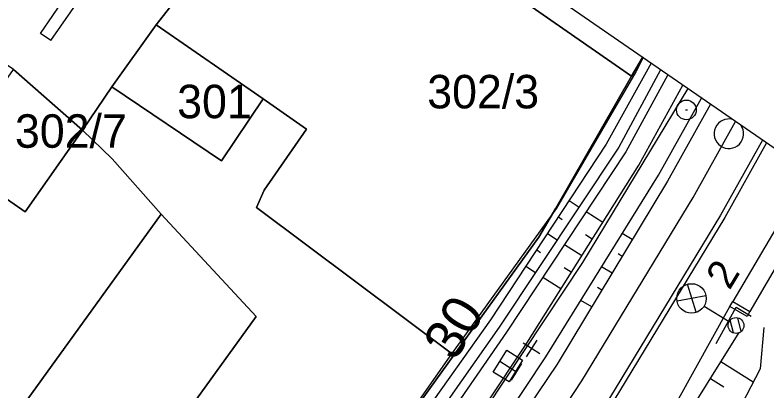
# Model space of a CAD drawing. Extents: x -558195 to -557985, y -1073457 to -1073198.
# Drawn here: x -558113.53 to -558075.28, y -1073322.92 to -1073303.83 of the extents above; entities that cross this region are included whole.
import ezdxf

# ---------------------------------------------------------------- set-up
doc = ezdxf.new("R2010")
doc.units = 0
for name, color, linetype in [('Default', 7, 'Continuous'), ('DWG-zabzař', 7, 'Continuous'), ('El2015-Sikl - patka - rampa', 7, 'Continuous'), ('El2015-Trakce', 7, 'Continuous'), ('Elektro nadzemní', 7, 'Continuous'), ('Kolej', 7, 'Continuous'), ('Nástupiště', 7, 'Continuous'), ('Návěst místo trati', 7, 'Continuous'), ('Plot - zábradlí', 7, 'Continuous'), ('Přejezd - štěrkové lože', 7, 'Continuous'), ('Rámeček stavby', 7, 'Continuous'), ('Sonda - šrafa - vrstevnice', 7, 'Continuous'), ('Svazek obcí údolí Desné', 7, 'Continuous'), ('Terén', 7, 'Continuous'), ('Vedení neurčené', 7, 'Continuous'), ('Vrstva 15', 7, 'Continuous'), ('Vrstva 16', 7, 'Continuous'), ('Vrstva 18', 7, 'Continuous'), ('Vrstva 28', 7, 'Continuous'), ('Zpevněná plocha - svah', 7, 'Continuous')]:
    doc.layers.add(name, color=color, linetype=linetype)

msp = doc.modelspace()

# ---------------------------------------------------------------- linework, layer by layer
at = {"layer": 'Default'}
for p, q in [((-558112.232, -1073304.762), (-558105.931, -1073295.618)), ((-558111.7, -1073305.129), (-558105.398, -1073295.985)), ((-558111.7, -1073305.129), (-558112.232, -1073304.762))]:
    msp.add_line(p, q, dxfattribs=at)
at = {"layer": 'DWG-zabzař'}
for p, q in [((-558079.305, -1073307.564), (-558084.66, -1073316.4)), ((-558084.66, -1073316.4), (-558091.64, -1073326.89))]:
    msp.add_line(p, q, dxfattribs=at)
at = {"layer": 'El2015-Sikl - patka - rampa'}
for p, q in [((-558088.512, -1073320.845), (-558087.712, -1073321.364)), ((-558088.401, -1073322.455), (-558089.212, -1073321.963))]:
    msp.add_line(p, q, dxfattribs=at)
for points in [[(-558087.712, -1073321.364), (-558088.401, -1073322.455), (-558089.212, -1073321.963), (-558088.512, -1073320.845), (-558087.712, -1073321.364)], [(-558089.212, -1073321.963), (-558089.212, -1073321.963), (-558088.512, -1073320.845), (-558088.512, -1073320.845)]]:
    msp.add_lwpolyline(points, dxfattribs=at)
at = {"layer": 'El2015-Trakce'}
for p, q in [((-558089.126, -1073321.835), (-558088.595, -1073320.988)), ((-558088.861, -1073321.412), (-558088.013, -1073321.942)), ((-558088.279, -1073322.366), (-558087.748, -1073321.519))]:
    msp.add_line(p, q, dxfattribs=at)
at = {"layer": 'Elektro nadzemní'}
for p, q in [((-558078.879, -1073318.925), (-558079.325, -1073317.502)), ((-558079.852, -1073318.351), (-558078.385, -1073318.079)), ((-558078.479, -1073318.608), (-558077.197, -1073319.387)), ((-558076.989, -1073319.969), (-558077.146, -1073319.324)), ((-558076.596, -1073319.894), (-558076.763, -1073319.207))]:
    msp.add_line(p, q, dxfattribs=at)
for centre, radius in [((-558079.12, -1073318.221), 0.749), ((-558076.855, -1073319.595), 0.4), ((-558076.855, -1073319.595), 0.4)]:
    msp.add_circle(centre, radius, dxfattribs=at)
at = {"layer": 'Kolej'}
msp.add_lwpolyline([(-558162.085, -1073435.464), (-558155.66, -1073426.127), (-558147.216, -1073413.854), (-558143.692, -1073408.727), (-558141.06, -1073404.904), (-558137.302, -1073399.438), (-558134.569, -1073395.461), (-558131.717, -1073391.307), (-558124.893, -1073381.375), (-558115.4, -1073367.564), (-558106.183, -1073354.164), (-558097.487, -1073341.511), (-558095.261, -1073338.268), (-558090.946, -1073331.927), (-558084.696, -1073322.399), (-558079.035, -1073313.091), (-558076.876, -1073309.237)], dxfattribs=at)
at = {"layer": 'Nástupiště'}
for points in [[(-558075.504, -1073310.182), (-558077.642, -1073314), (-558083.287, -1073323.291), (-558088.119, -1073330.713), (-558093.699, -1073338.955)], [(-558075.301, -1073310.322), (-558077.424, -1073314.112), (-558083.069, -1073323.403), (-558087.901, -1073330.825), (-558093.497, -1073339.112), (-558093.633, -1073339)], [(-558074.438, -1073314.006), (-558077.015, -1073318.379), (-558076.161, -1073318.88)], [(-558076.161, -1073318.88), (-558076.297, -1073319.14), (-558077.164, -1073318.639), (-558077.015, -1073318.379)], [(-558090.573, -1073339.885), (-558085.54, -1073332.431), (-558080.709, -1073325.01), (-558077.164, -1073318.639)]]:
    msp.add_lwpolyline(points, dxfattribs=at)
at = {"layer": 'Návěst místo trati'}
for p, q in [((-558079.431, -1073308.647), (-558079.331, -1073308.647)), ((-558086.99, -1073320.342), (-558087.526, -1073321.186)), ((-558086.836, -1073321.032), (-558087.68, -1073320.496))]:
    msp.add_line(p, q, dxfattribs=at)
msp.add_circle((-558079.381, -1073308.647), 0.5, dxfattribs=at)
msp.add_arc((-558077.223, -1073309.856), 0.75, 75.0246, 35.8535, dxfattribs=at)
at = {"layer": 'Plot - zábradlí'}
for points in [[(-558081.585, -1073305.993), (-558081.958, -1073306.712), (-558085.995, -1073313.64), (-558091.417, -1073321.151), (-558105.2, -1073340.829), (-558131.731, -1073378.073), (-558133.048, -1073381.894), (-558138.367, -1073389.952)], [(-558077.861, -1073320.516), (-558076.84, -1073318.669), (-558076.089, -1073319.12)]]:
    msp.add_lwpolyline(points, dxfattribs=at)
at = {"layer": 'Přejezd - štěrkové lože'}
for p, q in [((-558082.13, -1073315.231), (-558082.64, -1073314.923)), ((-558082.647, -1073316.087), (-558082.855, -1073315.961)), ((-558083.163, -1073316.943), (-558083.695, -1073316.622)), ((-558083.68, -1073317.799), (-558083.897, -1073317.668)), ((-558084.197, -1073318.655), (-558084.749, -1073318.322))]:
    msp.add_line(p, q, dxfattribs=at)
for points in [[(-558134.688, -1073392.469), (-558133.239, -1073389.979), (-558128.353, -1073382.563), (-558117.195, -1073366.537), (-558107.127, -1073351.64), (-558099.301, -1073340.237), (-558092.768, -1073330.583), (-558086.524, -1073321.182), (-558080.801, -1073311.959), (-558078.61, -1073308.043)], [(-558078.156, -1073308.355), (-558080.336, -1073312.26), (-558085.948, -1073321.555), (-558092.305, -1073330.965), (-558098.739, -1073340.644), (-558106.694, -1073352.203), (-558116.612, -1073366.808), (-558126.104, -1073380.52), (-558132.827, -1073390.228), (-558134.688, -1073392.469)]]:
    msp.add_lwpolyline(points, dxfattribs=at)
at = {"layer": 'Rámeček stavby'}
msp.add_lwpolyline([(-558106.904, -1073288.53), (-558048.067, -1073329.06), (-558134.478, -1073454.503), (-558193.315, -1073413.973)], close=True, dxfattribs=at)
at = {"layer": 'Sonda - šrafa - vrstevnice'}
for p, q in [((-558085.34, -1073313.249), (-558084.838, -1073313.58)), ((-558083.634, -1073314.358), (-558084.477, -1073313.826)), ((-558085.891, -1073314.084), (-558085.692, -1073314.215)), ((-558086.442, -1073314.918), (-558085.947, -1073315.244)), ((-558084.167, -1073315.204), (-558084.512, -1073314.986)), ((-558084.7, -1073316.05), (-558085.582, -1073315.494)), ((-558086.993, -1073315.752), (-558086.796, -1073315.882)), ((-558087.543, -1073316.587), (-558087.056, -1073316.909)), ((-558085.233, -1073316.896), (-558085.593, -1073316.669)), ((-558085.766, -1073317.742), (-558086.686, -1073317.162)), ((-558077.628, -1073321.432), (-558075.98, -1073322.461)), ((-558078.158, -1073322.281), (-558077.471, -1073322.71))]:
    msp.add_line(p, q, dxfattribs=at)
at = {"layer": 'Svazek obcí údolí Desné'}
msp.add_lwpolyline([(-558167.537, -1073431.708), (-558157.08, -1073415.91), (-558144.45, -1073397.61), (-558143.83, -1073396.83), (-558140.29, -1073392.34), (-558139.67, -1073391.56), (-558138.4, -1073389.94), (-558132.32, -1073380.12), (-558131.71, -1073378.11), (-558099.53, -1073332.65), (-558091.21, -1073321.1), (-558086.89, -1073315.11), (-558086.02, -1073313.63), (-558082.18, -1073306.93), (-558081.607, -1073305.978)], dxfattribs=at)
at = {"layer": 'Terén'}
for points in [[(-558081.18, -1073306.272), (-558083.456, -1073310.395), (-558089.337, -1073319.304), (-558095.797, -1073328.403), (-558102.651, -1073337.801)], [(-558080.693, -1073306.608), (-558082.815, -1073310.544), (-558088.899, -1073319.675), (-558095.32, -1073328.817), (-558102.006, -1073338.385), (-558110.752, -1073350.405)], [(-558080.325, -1073306.861), (-558082.46, -1073310.779), (-558088.525, -1073319.94), (-558094.874, -1073329.104), (-558101.386, -1073338.86), (-558109.505, -1073351.261), (-558119.112, -1073365.018), (-558130.44, -1073381.204), (-558136.541, -1073389.319), (-558138.367, -1073389.952)], [(-558141.446, -1073388.086), (-558138.672, -1073391.073), (-558136.007, -1073391.106), (-558129.583, -1073381.786), (-558118.096, -1073365.959), (-558108.152, -1073351.289), (-558100.315, -1073339.526), (-558093.751, -1073329.892), (-558087.503, -1073320.498), (-558081.802, -1073311.451), (-558079.554, -1073307.392)], [(-558075.447, -1073319.704), (-558075.635, -1073321.794), (-558078.439, -1073327.212), (-558083.002, -1073334.109), (-558086.852, -1073340.18), (-558089.38, -1073342.195)], [(-558090.522, -1073340.781), (-558084.963, -1073332.785), (-558079.942, -1073325.14), (-558076.703, -1073319.95)]]:
    msp.add_lwpolyline(points, dxfattribs=at)
at = {"layer": 'Vrstva 15'}
for points in [[(-558107.451, -1073289.376), (-558099.14, -1073295.15), (-558106.35, -1073304.33), (-558108.61, -1073307.47), (-558110.09, -1073309.68), (-558113.61, -1073306.59), (-558117.489, -1073303.948)], [(-558081.607, -1073305.978), (-558082.18, -1073306.93), (-558099.14, -1073295.15), (-558107.451, -1073289.376)], [(-558167.537, -1073431.708), (-558157.08, -1073415.91), (-558144.45, -1073397.61), (-558143.83, -1073396.83), (-558140.29, -1073392.34), (-558139.67, -1073391.56), (-558138.4, -1073389.94), (-558132.32, -1073380.12), (-558131.71, -1073378.11), (-558099.53, -1073332.65), (-558091.21, -1073321.1), (-558086.89, -1073315.11), (-558086.02, -1073313.63), (-558082.18, -1073306.93), (-558081.607, -1073305.978)], [(-558128.354, -1073319.721), (-558124.37, -1073322.4), (-558121.16, -1073317.67), (-558119.85, -1073318.64), (-558115.48, -1073312.12), (-558113.01, -1073313.83), (-558110.09, -1073309.68), (-558108.58, -1073311.13), (-558106.1, -1073313.94), (-558146.53, -1073369.85), (-558151.628, -1073353.507)]]:
    msp.add_lwpolyline(points, dxfattribs=at)
for points in [[(-558106.35, -1073304.33), (-558099.14, -1073295.15), (-558082.18, -1073306.93), (-558086.02, -1073313.63), (-558086.89, -1073315.11), (-558091.21, -1073321.1), (-558101.25, -1073313.61), (-558100.86, -1073312.72), (-558098.7, -1073309.62), (-558100.91, -1073308.09)], [(-558100.91, -1073308.09), (-558103.03, -1073311.24), (-558108.61, -1073307.47), (-558106.35, -1073304.33)], [(-558113.01, -1073313.83), (-558115.48, -1073312.12), (-558116.87, -1073311.27), (-558113.61, -1073306.59), (-558110.09, -1073309.68)], [(-558139.67, -1073391.56), (-558140.9, -1073387.37), (-558143.89, -1073378.07), (-558101.27, -1073319.14), (-558106.1, -1073313.94), (-558108.58, -1073311.13), (-558110.09, -1073309.68), (-558108.61, -1073307.47), (-558103.03, -1073311.24), (-558100.91, -1073308.09), (-558098.7, -1073309.62), (-558100.86, -1073312.72), (-558101.25, -1073313.61), (-558091.21, -1073321.1), (-558099.53, -1073332.65), (-558131.71, -1073378.11), (-558132.32, -1073380.12), (-558138.4, -1073389.94)], [(-558143.89, -1073378.07), (-558146.53, -1073369.85), (-558106.1, -1073313.94), (-558101.27, -1073319.14)]]:
    msp.add_lwpolyline(points, close=True, dxfattribs=at)
at = {"layer": 'Vrstva 16'}
msp.add_lwpolyline([(-558103.03, -1073311.24), (-558108.61, -1073307.47), (-558106.35, -1073304.33), (-558100.91, -1073308.09)], close=True, dxfattribs=at)
at = {"layer": 'Zpevněná plocha - svah'}
msp.add_lwpolyline([(-558074.109, -1073313.879), (-558068.665, -1073317.735), (-558068.829, -1073317.97), (-558073.627, -1073314.572), (-558076.161, -1073318.88)], dxfattribs=at)

# ---------------------------------------------------------------- texts
at = {"layer": 'El2015-Trakce'}
msp.add_text('30', height=2, rotation=57.9486, dxfattribs=at).set_placement((-558091.17, -1073321.472))
at = {"layer": 'Vedení neurčené'}
msp.add_text('2', height=1.5, rotation=58.7181, dxfattribs=at).set_placement((-558077.188, -1073317.844))
at = {"layer": 'Vrstva 18'}
for s, p in [('302/3', (-558092.56, -1073308.57)), ('302/7', (-558113.53, -1073310.57))]:
    msp.add_text(s, height=1.7, dxfattribs=at).set_placement(p)
at = {"layer": 'Vrstva 28'}
msp.add_text('301', height=1.7, dxfattribs=at).set_placement((-558105.28, -1073309.07))

doc.saveas('drawing.dxf')
